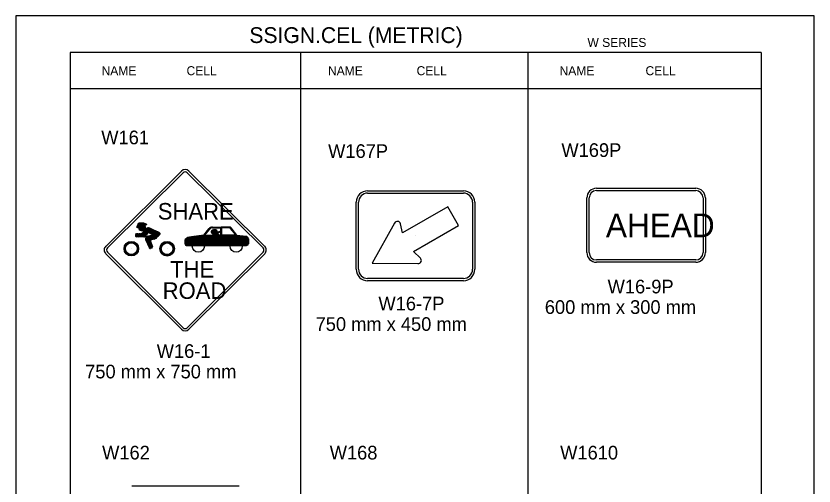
# Model space of a CAD drawing. Extents: x -12 to 6962, y -3756 to 679.
# Drawn here: x 1549.2 to 1724.4, y -586.2 to -483 of the extents above; entities that cross this region are included whole.
import ezdxf

# ---------------------------------------------------------------- set-up
doc = ezdxf.new("R2010")
doc.units = 0
for name, color, linetype in [('Level 1', 7, 'Continuous'), ('Level 2', 7, 'Continuous'), ('Level 3', 7, 'Continuous'), ('Level 62', 7, 'Continuous')]:
    doc.layers.add(name, color=color, linetype=linetype)

msp = doc.modelspace()

# ---------------------------------------------------------------- linework, layer by layer
at = {"layer": 'Level 1'}
for p, q in [((1712.82, -491.06), (1561.06, -491.06)), ((1561.06, -491.06), (1561.06, -691.06)), ((1611.65, -491.06), (1611.65, -691.06)), ((1661.63, -491.06), (1661.63, -691.06)), ((1712.82, -491.06), (1712.82, -691.06)), ((1712.82, -498.98), (1561.06, -498.98)), ((1585.54, -517.06), (1568.91, -533.59)), ((1585.89, -517.42), (1569.26, -533.94)), ((1603.47, -533.94), (1586.79, -517.42)), ((1603.83, -533.59), (1587.14, -517.06)), ((1626.42, -521.41), (1647.45, -521.41)), ((1626.42, -521.91), (1647.45, -521.91)), ((1676.67, -520.85), (1698.46, -520.85)), ((1676.67, -521.35), (1698.46, -521.35)), ((1623.92, -538.63), (1623.92, -523.91)), ((1624.42, -538.63), (1624.42, -523.91)), ((1649.45, -523.91), (1649.45, -538.63)), ((1649.95, -523.91), (1649.95, -538.63)), ((1674.55, -534.96), (1674.55, -522.97)), ((1675.05, -534.96), (1675.05, -522.97)), ((1700.08, -522.97), (1700.08, -534.96)), ((1700.58, -522.97), (1700.58, -534.96)), ((1575.82, -529.13), (1576.51, -528.45)), ((1575.82, -529.18), (1576.57, -528.45)), ((1575.82, -529.3), (1576.67, -528.45)), ((1575.82, -529.35), (1576.72, -528.45)), ((1575.82, -529.4), (1576.78, -528.45)), ((1575.82, -529.46), (1576.88, -528.45)), ((1575.82, -529.08), (1576.41, -528.5)), ((1575.82, -529.56), (1576.93, -528.5)), ((1575.82, -529.56), (1575.82, -529.18)), ((1575.93, -528.92), (1576.3, -528.55)), ((1575.93, -528.82), (1576.2, -528.61)), ((1575.98, -529.56), (1577, -528.55)), ((1575.98, -528.71), (1576.08, -528.61)), ((1576.03, -529.46), (1577.05, -528.55)), ((1576.08, -529.46), (1577.15, -528.55)), ((1576.08, -529.56), (1577.21, -528.55)), ((1576.15, -529.61), (1577.26, -528.55)), ((1576.2, -529.67), (1577.26, -528.55)), ((1576.2, -529.77), (1577.31, -528.61)), ((1576.2, -529.77), (1577.42, -528.61)), ((1576.25, -529.82), (1577.47, -528.61)), ((1576.25, -529.88), (1577.52, -528.61)), ((1576.3, -529.88), (1577.52, -528.66)), ((1576.3, -529.93), (1577.63, -528.66)), ((1576.41, -529.93), (1577.68, -528.66)), ((1576.41, -530.03), (1577.73, -528.71)), ((1576.46, -530.03), (1577.52, -529.03)), ((1576.51, -530.1), (1577.52, -529.03)), ((1576.51, -530.1), (1577.52, -529.08)), ((1576.57, -530.1), (1577.57, -529.13)), ((1576.67, -530.15), (1577.63, -529.18)), ((1576.72, -530.15), (1577.63, -529.25)), ((1577.95, -528.82), (1577.47, -529.03)), ((1577.52, -528.97), (1577.73, -528.71)), ((1577.63, -528.92), (1577.78, -528.71)), ((1577.73, -528.87), (1577.9, -528.82)), ((1577.9, -528.82), (1577.95, -528.82)), ((1577.9, -528.87), (1577.9, -528.82)), ((1687.56, -528.96), (1687.56, -528.96)), ((1575.51, -531.31), (1575.98, -530.78)), ((1575.51, -531.37), (1576.03, -530.78)), ((1575.51, -531.47), (1576.08, -530.78)), ((1575.51, -530.88), (1575.56, -530.83)), ((1575.51, -531.05), (1575.72, -530.83)), ((1575.51, -531.1), (1575.77, -530.83)), ((1575.51, -531.16), (1575.82, -530.83)), ((1575.51, -531.26), (1575.93, -530.83)), ((1575.56, -531.47), (1576.2, -530.78)), ((1575.56, -531.52), (1576.3, -530.78)), ((1575.61, -531.52), (1576.41, -530.78)), ((1575.66, -530.83), (1576.78, -530.78)), ((1575.72, -531.52), (1576.46, -530.78)), ((1575.72, -530.83), (1575.72, -530.83)), ((1575.77, -531.52), (1576.51, -530.78)), ((1576.08, -529.46), (1575.82, -529.56)), ((1575.82, -531.52), (1576.57, -530.78)), ((1575.93, -531.52), (1576.67, -530.78)), ((1575.98, -531.52), (1576.72, -530.78)), ((1576.03, -531.52), (1576.88, -530.78)), ((1576.08, -531.52), (1578.11, -529.56)), ((1576.2, -531.52), (1578.21, -529.56)), ((1576.25, -531.52), (1578.27, -529.56)), ((1576.36, -531.52), (1578.37, -529.56)), ((1576.41, -531.52), (1578.42, -529.56)), ((1576.51, -531.52), (1578.48, -529.56)), ((1576.57, -531.52), (1578.48, -529.56)), ((1576.67, -531.52), (1578.58, -529.61)), ((1576.72, -531.52), (1578.63, -529.61)), ((1576.78, -530.15), (1577.63, -529.3)), ((1576.78, -531.52), (1578.63, -529.61)), ((1576.88, -530.15), (1577.63, -529.4)), ((1576.88, -531.52), (1578.7, -529.67)), ((1576.93, -530.15), (1577.63, -529.46)), ((1576.93, -531.52), (1578.75, -529.67)), ((1577, -530.15), (1577.63, -529.56)), ((1577, -531.52), (1578.85, -529.67)), ((1577, -530.67), (1577.85, -529.72)), ((1577.05, -530.15), (1577.63, -529.61)), ((1577.05, -531.52), (1578.85, -529.77)), ((1577.15, -531.52), (1578.91, -529.77)), ((1577.21, -530.1), (1577.52, -529.77)), ((1577.21, -531.52), (1578.96, -529.77)), ((1577.26, -531.52), (1579.01, -529.82)), ((1577.42, -530.25), (1578, -529.61)), ((1578.21, -530.57), (1577.52, -531.42)), ((1577.73, -529.82), (1577.9, -529.61)), ((1577.95, -532.7), (1580.28, -530.36)), ((1577.95, -532.75), (1580.33, -530.36)), ((1577.95, -532.8), (1580.4, -530.36)), ((1578, -532.86), (1580.45, -530.41)), ((1578.21, -530.57), (1578.21, -530.57)), ((1578.21, -530.57), (1578.21, -530.57)), ((1579.43, -531.1), (1578.21, -530.57)), ((1578.27, -530.62), (1579.06, -529.82)), ((1578.32, -530.62), (1579.12, -529.82)), ((1578.37, -530.62), (1579.17, -529.88)), ((1578.42, -530.67), (1579.22, -529.88)), ((1578.48, -530.67), (1579.27, -529.88)), ((1578.53, -529.56), (1580.66, -530.52)), ((1578.53, -530.67), (1579.33, -529.93)), ((1578.58, -530.73), (1579.38, -529.93)), ((1578.63, -530.78), (1579.43, -529.93)), ((1578.7, -530.78), (1579.43, -529.98)), ((1578.7, -532.22), (1580.45, -530.41)), ((1578.75, -530.78), (1579.48, -530.03)), ((1578.75, -530.83), (1579.6, -530.03)), ((1578.85, -530.83), (1579.65, -530.03)), ((1578.85, -532.22), (1580.55, -530.41)), ((1578.91, -530.88), (1579.65, -530.1)), ((1578.91, -532.11), (1580.61, -530.46)), ((1578.96, -530.88), (1579.7, -530.1)), ((1578.96, -530.88), (1579.81, -530.1)), ((1579.01, -530.88), (1579.86, -530.15)), ((1579.01, -532.11), (1580.66, -530.52)), ((1579.12, -531), (1579.86, -530.15)), ((1579.12, -531), (1579.91, -530.15)), ((1579.12, -532.11), (1580.66, -530.52)), ((1579.17, -531), (1579.97, -530.25)), ((1579.17, -532.06), (1580.71, -530.57)), ((1579.22, -531.05), (1580.02, -530.25)), ((1579.33, -531.05), (1580.07, -530.25)), ((1579.33, -531.05), (1580.12, -530.31)), ((1579.33, -532.06), (1580.71, -530.57)), ((1579.38, -531.1), (1580.18, -530.31)), ((1579.43, -531.1), (1580.23, -530.31)), ((1580.07, -531.37), (1580.82, -530.62)), ((1580.07, -531.37), (1580.82, -530.62)), ((1580.12, -531.37), (1580.82, -530.67)), ((1580.18, -531.47), (1580.87, -530.78)), ((1580.28, -531.47), (1580.82, -530.83)), ((1580.76, -531), (1580.5, -531.31)), ((1590.43, -531.16), (1591.55, -529.77)), ((1590.43, -531.26), (1591.6, -529.82)), ((1590.53, -531.26), (1591.6, -529.82)), ((1590.53, -531.31), (1591.71, -529.88)), ((1590.53, -531.31), (1591.71, -529.88)), ((1590.65, -531.16), (1591.71, -529.88)), ((1592.35, -529.35), (1594.26, -529.35)), ((1592.35, -529.4), (1594.26, -529.4)), ((1592.35, -529.46), (1594.26, -529.46)), ((1592.35, -529.51), (1594.26, -529.51)), ((1592.35, -529.56), (1594.21, -529.56)), ((1594.26, -530.25), (1592.61, -530.83)), ((1594.15, -530.25), (1592.61, -530.78)), ((1592.61, -530.52), (1593.46, -530.25)), ((1592.61, -530.57), (1593.46, -530.31)), ((1592.61, -530.62), (1593.46, -530.36)), ((1592.66, -530.62), (1593.41, -530.41)), ((1592.72, -530.67), (1594.21, -530.25)), ((1594.21, -530.31), (1592.93, -530.78)), ((1594.21, -530.36), (1593.03, -530.78)), ((1594.21, -530.41), (1593.25, -530.78)), ((1594.21, -531.16), (1594.21, -529.56)), ((1594.21, -530.25), (1594.21, -530.41)), ((1596.06, -529.35), (1594.26, -529.35)), ((1596.06, -529.4), (1594.26, -529.4)), ((1596.06, -529.46), (1594.26, -529.46)), ((1596.06, -529.51), (1594.26, -529.51)), ((1594.26, -531.16), (1594.26, -529.56)), ((1594.31, -531.16), (1594.31, -529.56)), ((1594.31, -531.16), (1594.31, -529.56)), ((1596.06, -529.56), (1594.42, -529.56)), ((1594.42, -531.16), (1594.42, -529.56)), ((1597.55, -531.16), (1596.33, -529.67)), ((1597.66, -531.26), (1596.38, -529.61)), ((1597.61, -531.31), (1596.38, -529.67)), ((1597.66, -531.26), (1596.43, -529.61)), ((1597.71, -531.16), (1596.48, -529.56)), ((1575.51, -531.31), (1575.51, -531.05)), ((1577.26, -531.52), (1575.72, -531.52)), ((1577.42, -531.52), (1577.78, -531.1)), ((1577.47, -531.47), (1577.47, -531.47)), ((1577.68, -532.22), (1578.7, -531.16)), ((1577.68, -532.01), (1578.42, -531.26)), ((1577.68, -532.06), (1578.48, -531.26)), ((1577.68, -532.11), (1578.58, -531.26)), ((1577.68, -531.85), (1578.21, -531.31)), ((1577.68, -531.95), (1578.27, -531.31)), ((1577.68, -531.8), (1578.11, -531.37)), ((1577.73, -532.32), (1578.96, -531.1)), ((1577.73, -532.27), (1578.75, -531.16)), ((1577.73, -532.27), (1578.91, -531.16)), ((1577.73, -531.63), (1578, -531.37)), ((1578.48, -533.92), (1577.73, -532.16)), ((1577.78, -532.37), (1579.06, -531.1)), ((1577.78, -532.48), (1579.17, -531.1)), ((1577.78, -532.48), (1579.22, -531.1)), ((1577.9, -532.53), (1579.33, -531.1)), ((1577.9, -532.58), (1579.38, -531.1)), ((1577.9, -532.65), (1579.43, -531.1)), ((1578, -532.86), (1578.63, -532.27)), ((1578, -532.96), (1578.7, -532.32)), ((1578.11, -531.37), (1578.96, -531.16)), ((1578.11, -533.01), (1578.7, -532.32)), ((1578.11, -533.01), (1578.7, -532.37)), ((1578.11, -533.07), (1578.75, -532.48)), ((1578.16, -533.17), (1578.75, -532.53)), ((1578.16, -533.22), (1578.75, -532.58)), ((1578.16, -533.22), (1578.75, -532.58)), ((1578.16, -533.28), (1578.8, -532.7)), ((1578.21, -533.33), (1578.85, -532.75)), ((1578.21, -533.38), (1578.85, -532.8)), ((1579.91, -531.9), (1578.63, -532.22)), ((1578.63, -532.22), (1579.17, -533.71)), ((1579.33, -531.05), (1579.33, -531.05)), ((1579.38, -532.01), (1580.02, -531.37)), ((1579.48, -532.01), (1580.07, -531.47)), ((1579.6, -532.01), (1580.07, -531.47)), ((1579.65, -531.95), (1580.12, -531.52)), ((1579.81, -531.95), (1580.12, -531.58)), ((1579.86, -531.95), (1580.12, -531.63)), ((1579.91, -531.85), (1580.07, -531.73)), ((1579.91, -531.85), (1580.07, -531.73)), ((1579.97, -531.85), (1580.07, -531.8)), ((1580.12, -531.42), (1580.02, -531.37)), ((1580.4, -531.37), (1580.66, -531.1)), ((1586.35, -532.11), (1600.26, -532.11)), ((1586.35, -533.01), (1586.35, -532.11)), ((1586.35, -532.32), (1600.26, -532.32)), ((1586.35, -532.53), (1600.26, -532.53)), ((1586.35, -532.75), (1600.26, -532.75)), ((1586.4, -533.01), (1586.4, -532.11)), ((1586.45, -533.01), (1586.45, -532.11)), ((1586.45, -533.01), (1586.45, -532.11)), ((1586.56, -533.01), (1586.56, -532.11)), ((1586.61, -533.01), (1586.61, -532.11)), ((1586.66, -533.01), (1586.66, -532.11)), ((1586.66, -533.01), (1586.66, -532.11)), ((1586.71, -532.01), (1599.83, -532.01)), ((1586.71, -532.01), (1599.83, -532.01)), ((1586.71, -532.06), (1599.83, -532.06)), ((1586.71, -532.11), (1599.83, -532.11)), ((1586.71, -532.22), (1599.83, -532.22)), ((1586.71, -532.22), (1599.83, -532.22)), ((1586.71, -532.27), (1599.83, -532.27)), ((1586.71, -532.32), (1599.83, -532.32)), ((1586.71, -532.37), (1599.83, -532.37)), ((1586.71, -532.37), (1599.83, -532.37)), ((1586.71, -532.48), (1599.83, -532.48)), ((1586.71, -532.53), (1599.83, -532.53)), ((1586.71, -532.58), (1599.83, -532.58)), ((1586.71, -532.58), (1599.83, -532.58)), ((1586.71, -532.7), (1599.83, -532.7)), ((1586.71, -532.75), (1599.83, -532.75)), ((1586.71, -532.8), (1599.83, -532.8)), ((1586.71, -532.8), (1599.83, -532.8)), ((1586.87, -531.95), (1599.83, -531.95)), ((1586.92, -531.85), (1599.83, -531.85)), ((1587.41, -531.8), (1599.83, -531.8)), ((1587.56, -531.8), (1599.83, -531.8)), ((1590.43, -531.16), (1587.72, -531.47)), ((1590.43, -531.26), (1587.72, -531.52)), ((1590.43, -531.31), (1587.72, -531.58)), ((1590.43, -531.37), (1587.72, -531.63)), ((1590.43, -531.37), (1587.72, -531.68)), ((1590.43, -531.47), (1587.72, -531.73)), ((1587.88, -531.73), (1598.18, -531.73)), ((1587.93, -531.47), (1587.93, -531.47)), ((1590.43, -531.52), (1588.47, -531.73)), ((1590.43, -531.52), (1588.95, -531.73)), ((1590.43, -531.58), (1589.53, -531.73)), ((1590.43, -531.63), (1589.85, -531.73)), ((1590.43, -531.16), (1590.43, -531.16)), ((1590.43, -531.26), (1598.18, -531.26)), ((1590.43, -531.31), (1598.18, -531.31)), ((1590.43, -531.37), (1598.18, -531.37)), ((1590.43, -531.37), (1598.18, -531.37)), ((1590.43, -531.52), (1598.18, -531.52)), ((1590.43, -531.58), (1598.18, -531.58)), ((1590.43, -531.58), (1598.18, -531.58)), ((1590.43, -531.63), (1598.18, -531.63)), ((1590.48, -531.47), (1598.18, -531.47)), ((1590.65, -531.16), (1594.21, -531.16)), ((1590.7, -533.43), (1590.7, -531.16)), ((1597.55, -531.16), (1594.42, -531.16)), ((1597.66, -531.52), (1599.62, -531.8)), ((1597.66, -531.58), (1599.62, -531.8)), ((1597.66, -531.63), (1599.62, -531.85)), ((1597.71, -531.16), (1597.71, -531.16)), ((1597.71, -531.16), (1599.73, -531.37)), ((1597.71, -531.26), (1599.73, -531.47)), ((1597.71, -531.31), (1599.73, -531.52)), ((1597.71, -531.37), (1599.73, -531.58)), ((1597.71, -531.37), (1599.73, -531.58)), ((1597.71, -531.47), (1599.73, -531.63)), ((1597.71, -531.52), (1599.67, -531.73)), ((1599.83, -531.95), (1599.83, -533.01)), ((1599.88, -531.95), (1599.88, -533.01)), ((1599.88, -531.95), (1599.88, -533.01)), ((1600, -531.95), (1600, -533.01)), ((1600.05, -531.95), (1600.05, -533.01)), ((1600.1, -531.95), (1600.1, -533.01)), ((1600.1, -531.95), (1600.1, -533.01)), ((1600.21, -531.95), (1600.21, -533.01)), ((1600.26, -531.95), (1600.26, -533.01)), ((1636.99, -531.29), (1636.99, -531.29)), ((1574.5, -534.07), (1574.5, -534.07)), ((1578.27, -533.43), (1578.85, -532.86)), ((1578.27, -533.5), (1578.85, -532.86)), ((1578.27, -533.55), (1578.91, -532.96)), ((1578.32, -533.6), (1578.91, -533.01)), ((1578.37, -533.65), (1578.91, -533.07)), ((1578.37, -533.71), (1578.96, -533.12)), ((1578.37, -533.76), (1578.96, -533.17)), ((1578.42, -533.76), (1578.96, -533.22)), ((1578.42, -533.81), (1578.96, -533.28)), ((1578.48, -533.92), (1579.01, -533.33)), ((1578.48, -533.97), (1579.01, -533.38)), ((1578.48, -533.97), (1579.01, -533.43)), ((1578.58, -534.02), (1579.06, -533.5)), ((1578.58, -534.02), (1579.12, -533.55)), ((1578.58, -534.07), (1578.58, -534.07)), ((1578.63, -534.07), (1579.12, -533.65)), ((1578.7, -534.02), (1579.12, -533.65)), ((1579.01, -533.97), (1578.75, -534.07)), ((1578.85, -534.02), (1579.12, -533.71)), ((1578.96, -533.97), (1579.17, -533.76)), ((1579.01, -533.97), (1579.12, -533.92)), ((1579.01, -533.97), (1579.01, -533.97)), ((1579.12, -533.92), (1579.12, -533.92)), ((1582.41, -534.07), (1582.41, -534.07)), ((1586.35, -532.96), (1600.26, -532.96)), ((1586.35, -533.17), (1600.26, -533.17)), ((1586.36, -534.38), (1586.36, -534.38)), ((1586.71, -532.86), (1599.83, -532.86)), ((1586.71, -532.96), (1599.83, -532.96)), ((1586.71, -533.01), (1599.83, -533.01)), ((1586.71, -533.01), (1599.83, -533.01)), ((1586.71, -533.07), (1599.83, -533.07)), ((1586.71, -533.17), (1599.83, -533.17)), ((1586.71, -533.22), (1599.83, -533.22)), ((1586.71, -533.22), (1599.83, -533.22)), ((1586.71, -533.28), (1599.83, -533.28)), ((1586.71, -533.33), (1599.83, -533.33)), ((1586.71, -533.43), (1599.83, -533.43)), ((1586.82, -533.43), (1599.73, -533.43)), ((1589.42, -533.43), (1589.42, -533.43)), ((1568.91, -535.2), (1585.57, -551.8)), ((1569.26, -534.85), (1585.92, -551.45)), ((1586.82, -551.45), (1603.47, -534.85)), ((1587.17, -551.8), (1603.83, -535.2)), ((1698.46, -536.58), (1676.67, -536.58)), ((1698.46, -537.08), (1676.67, -537.08)), ((1647.45, -540.63), (1626.42, -540.63)), ((1647.45, -541.13), (1626.42, -541.13)), ((1598.18, -586.21), (1574.65, -586.21))]:
    msp.add_line(p, q, dxfattribs=at)
for centre, radius in [((1574.52, -534.1), 1.6), ((1574.52, -534.1), 1.55), ((1574.52, -534.1), 1.5), ((1574.52, -534.1), 1.44), ((1574.52, -534.1), 1.4), ((1574.52, -534.1), 1.33), ((1582.38, -534.11), 1.6), ((1582.38, -534.13), 1.6), ((1582.38, -534.13), 1.56), ((1582.38, -534.13), 1.51), ((1582.38, -534.13), 1.47), ((1582.38, -534.13), 1.43), ((1582.38, -534.13), 1.39), ((1582.38, -534.13), 1.35), ((1589.24, -533.55), 1.33), ((1597.53, -533.55), 1.33), ((1574.52, -534.1), 1.28), ((1582.38, -534.13), 1.31), ((1582.38, -534.13), 1.28)]:
    msp.add_circle(centre, radius, dxfattribs=at)
for centre, radius, start, end in [((1586.34, -517.87), 1.14, 45.275, 134.8164), ((1586.34, -517.87), 0.638, 45.275, 134.8164), ((1626.42, -523.91), 2.5, 90, 180), ((1626.42, -523.91), 2, 90, 180), ((1647.45, -523.91), 2.5, 0, 90), ((1647.45, -523.91), 2, 0, 90), ((1676.67, -522.97), 2.12, 90, 180), ((1676.67, -522.97), 1.62, 90, 180), ((1698.46, -522.97), 2.12, 0, 90), ((1698.46, -522.97), 1.62, 0, 90), ((1576.51, -529.14), 0.668, 88.4815, 184.503), ((1576.86, -529.4), 0.757, 184.7336, 34.5794), ((1576.69, -530.91), 2.44, 59.3444, 93.6804), ((1575.67, -531.02), 0.204, 93.0716, 180), ((1576.73, -530.45), 0.306, 273.0688, 317.9211), ((1578.26, -530.13), 0.612, 66.6719, 137.9206), ((1580.51, -530.79), 0.301, 318.1552, 66.9025), ((1592.34, -530.37), 1.02, 90, 142.4675), ((1592.34, -530.37), 0.969, 90, 142.4675), ((1592.34, -530.37), 0.918, 90, 142.4675), ((1592.34, -530.37), 0.867, 90, 142.4675), ((1592.34, -530.37), 0.829, 90, 142.4675), ((1591.91, -530.15), 1.04, 272.2964, 318.7927), ((1591.91, -530.15), 1.09, 272.2964, 318.7927), ((1591.91, -530.15), 1.14, 272.2964, 318.7927), ((1591.91, -530.15), 1.19, 272.2964, 318.7927), ((1591.91, -530.15), 1.24, 272.2964, 318.7927), ((1591.91, -530.15), 1.29, 272.2964, 318.7927), ((1591.91, -530.15), 1.34, 272.2964, 318.7927), ((1593.07, -531.78), 1.02, 35.4101, 112.3395), ((1593.07, -531.78), 0.972, 35.4101, 112.3395), ((1593.07, -531.78), 0.921, 35.4101, 112.3395), ((1593.07, -531.78), 0.87, 35.4101, 112.3395), ((1593.07, -531.78), 0.819, 35.4101, 112.3395), ((1593.07, -531.78), 0.768, 35.4101, 112.3395), ((1596.06, -529.86), 0.51, 37.5314, 90), ((1596.06, -529.86), 0.459, 37.5314, 90), ((1596.06, -529.86), 0.408, 37.5314, 90), ((1596.06, -529.86), 0.357, 37.5314, 90), ((1596.06, -529.85), 0.309, 37.5314, 90), ((1575.67, -531.31), 0.204, 180, 270), ((1577.26, -531.21), 0.306, 270, 318.1571), ((1578.25, -531.94), 0.612, 104.3023, 204.0018), ((1579.3, -532.12), 1.03, 83.7523, 110.8125), ((1579.8, -531.6), 0.308, 286.2905, 47.5031), ((1580.21, -531.1), 0.332, 250.3384, 321.5524), ((1593.07, -531.78), 0.717, 35.4101, 112.3395), ((1593.07, -531.78), 0.666, 35.4101, 112.3395), ((1599.61, -532.03), 0.281, 11.5469, 82.3118), ((1599.61, -532.03), 0.383, 11.5469, 82.3118), ((1599.61, -532.03), 0.332, 11.5469, 82.3118), ((1599.61, -532.03), 0.434, 11.5469, 82.3118), ((1599.61, -532.03), 0.536, 11.5469, 82.3118), ((1599.61, -532.03), 0.485, 11.5469, 82.3118), ((1599.61, -532.03), 0.587, 11.5469, 82.3118), ((1599.61, -532.03), 0.638, 11.5469, 82.3118), ((1569.71, -534.39), 1.14, 134.8164, 225.0917), ((1569.71, -534.39), 0.638, 134.8164, 225.0917), ((1578.66, -533.85), 0.204, 203.9931, 288.842), ((1578.94, -533.76), 0.204, 288.8543, 18.4168), ((1586.74, -533.04), 0.399, 176.1859, 266.1859), ((1586.75, -532.98), 0.357, 180, 270), ((1586.75, -532.98), 0.306, 180, 270), ((1586.75, -532.98), 0.255, 180, 270), ((1586.75, -532.98), 0.204, 180, 270), ((1586.75, -532.98), 0.153, 180, 270), ((1586.75, -532.98), 0.102, 180, 270), ((1586.75, -532.98), 0.051, 180, 270), ((1599.83, -532.98), 0.408, 270, 0), ((1599.83, -532.98), 0.357, 270, 0), ((1599.83, -532.98), 0.306, 270, 0), ((1599.83, -532.98), 0.255, 270, 0), ((1599.83, -532.98), 0.204, 270, 0), ((1599.83, -532.98), 0.153, 270, 0), ((1599.83, -532.98), 0.102, 270, 0), ((1599.83, -532.98), 0.051, 270, 0), ((1603.02, -534.39), 0.637, 314.9086, 45.275), ((1603.02, -534.39), 1.14, 314.9086, 45.275), ((1676.67, -534.96), 2.12, 180, 270), ((1676.67, -534.96), 1.62, 180, 270), ((1698.46, -534.96), 1.62, 270, 0), ((1698.46, -534.96), 2.12, 270, 0), ((1626.42, -538.63), 2.5, 180, 270), ((1626.42, -538.63), 2, 180, 270), ((1647.45, -538.63), 2, 270, 0), ((1647.45, -538.63), 2.5, 270, 0), ((1586.37, -551), 1.14, 225.0917, 314.9086), ((1586.37, -551), 0.638, 225.0917, 314.9086)]:
    msp.add_arc(centre, radius, start, end, dxfattribs=at)
for centre, major_axis, ratio, start_param, end_param in [((1592.75, -530.4), (-0.701, 0.021), 0.656276, 3.120994, 7.708521), ((1592.75, -530.4), (-0.65, 0.019), 0.629337, 3.120994, 7.708521), ((1592.75, -530.4), (-0.599, 0.018), 0.597818, 3.120994, 7.708521), ((1592.75, -530.4), (-0.548, 0.016), 0.56044, 3.120994, 7.708521), ((1592.75, -530.4), (-0.498, 0.015), 0.515402, 3.120994, 7.708521), ((1592.75, -530.4), (-0.447, 0.013), 0.460081, 3.120994, 7.708521), ((1592.75, -530.4), (-0.396, 0.012), 0.390502, 3.120994, 7.708521), ((1592.75, -530.4), (-0.345, 0.01), 0.300337, 3.120994, 7.708521), ((1592.75, -530.4), (-0.294, 0.009), 0.178863, 3.120994, 7.708521), ((1592.75, -530.4), (-0.243, 0.007), 0.006348, 3.120994, 7.708521), ((1592.75, -530.4), (-0.548, 0.016), 0.56044, 2.348331, 2.578157), ((1587.86, -532.88), (-1.8, 0), 0.782928, 4.798996, 5.70662), ((1587.86, -532.88), (-1.75, 0), 0.776616, 4.798996, 5.70662), ((1587.86, -532.88), (-1.7, 0), 0.769926, 4.798996, 5.70662), ((1587.86, -532.88), (-1.65, 0), 0.762824, 4.798996, 5.70662), ((1587.86, -532.88), (-1.6, 0), 0.755269, 4.798996, 5.70662), ((1587.87, -532.88), (-1.55, 0), 0.747216, 4.798996, 5.70662)]:
    msp.add_ellipse(centre, major_axis=major_axis, ratio=ratio, start_param=start_param, end_param=end_param, dxfattribs=at)
at = {"layer": 'Level 3'}
for p, q in [((1644.05, -524.89), (1634.09, -530.66)), ((1646.36, -529.03), (1644.05, -524.89)), ((1632.34, -528.5), (1627.41, -537.28)), ((1634.09, -530.66), (1633.63, -528.63)), ((1636.47, -534.72), (1646.36, -529.03)), ((1638, -536.17), (1636.47, -534.72)), ((1627.41, -537.28), (1637.48, -537.36))]:
    msp.add_line(p, q, dxfattribs=at)
for centre, start, end in [((1632.96, -528.79), 13.5359, 154.6538), ((1637.53, -536.67), 265.5395, 46.6575)]:
    msp.add_arc(centre, 0.689, start, end, dxfattribs=at)
at = {"layer": 'Level 62'}
msp.add_lwpolyline([(1549.19, -696.11), (1724.45, -696.11), (1724.45, -483.01), (1549.19, -483.01)], close=True, dxfattribs=at)

# ---------------------------------------------------------------- texts
at = {"layer": 'Level 1'}
for s, height, p in [('SHARE', 3.62, (1580.33, -527.7)), ('AHEAD', 5.185, (1678.74, -531.58)), ('THE', 3.62, (1583.05, -540.45)), ('ROAD', 3.62, (1581.4, -545.12))]:
    msp.add_text(s, height=height, dxfattribs=at).set_placement(p)
at = {"layer": 'Level 2'}
for s, p in [('W161', (1567.92, -511.18)), ('W167P', (1617.74, -514.18)), ('W169P', (1668.97, -513.96)), ('W162', (1568.11, -580.38)), ('W168', (1618.09, -580.38)), ('W1610', (1668.7, -580.38))]:
    msp.add_text(s, height=3, dxfattribs=at).set_placement(p)
at = {"layer": 'Level 3'}
for s, height, p in [('SSIGN.CEL (METRIC)', 3.4642, (1600.45, -488.95)), ('W SERIES', 1.979, (1674.69, -489.82)), ('NAME', 1.98, (1567.98, -496.02)), ('CELL', 1.98, (1586.65, -496.02)), ('NAME', 1.98, (1617.71, -496.02)), ('CELL', 1.98, (1637.17, -496.02)), ('NAME', 1.98, (1668.56, -496.02)), ('CELL', 1.98, (1687.44, -496.02)), ('W16-9P', 3, (1679.12, -543.92)), ('W16-7P', 3, (1628.79, -547.65)), ('600 mm x 300 mm', 3, (1665.33, -548.42)), ('750 mm x 450 mm', 3, (1614.99, -552.15)), ('W16-1', 3, (1580.1, -558.08)), ('750 mm x 750 mm', 3, (1564.38, -562.58))]:
    msp.add_text(s, height=height, dxfattribs=at).set_placement(p)

doc.saveas('drawing.dxf')
